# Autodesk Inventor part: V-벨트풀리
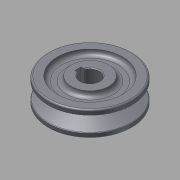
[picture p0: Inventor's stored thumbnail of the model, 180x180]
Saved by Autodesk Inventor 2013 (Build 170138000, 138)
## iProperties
Created: 2015-12
Part Number: V-벨트풀리
Material: 강철, 연강
Document SubType Name: Modeling
Designer: mdu
Density: 7.86 g/cm^3
Mass: 156.955 g
Surface Area: 99.5161 cm^2
Volume: 19.9688 cm^3
CustomPartVersion: 1
Author: mdu
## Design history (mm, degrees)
sketch "주 스케치"
  geometry: L1 (0, 16)-(27, 16); L2 (27, 16)-(27, 12.861); L3 (27, 12.861)-(16, 9.498); L4 (16, 9.498)-(16, 6.502); L5 (16, 6.502)-(27, 3.139); L6 (27, 3.139)-(27, 0); L7 (27, 0)-(0, 0); L8 (25, 12.25)-(25, 3.75); L9 (16, 8)-(25, 8); L10 (27, 12.861)-(27, 3.139); L11 (0, -3)-(0, 18) reference; L12 (0, 0)-(0, 16)
  constraints: 22 end point, 5 perpendicular, 2 collinear, 2 midpoint, 2 point on line, 1 parallel
  dimensions: "d0" = 8.5 distance of L8.start L8.end (= da_Bw); "d1" = 34 deg angle of L3 L5 (= da_Alfa); "d2" = 2 distance between parallel lines of L2 L8 (= da_c); "d6" = 16 distance between parallel lines of L7 L1 (computed from d5, da_ng, da_Sg); "d21" = 50 diameter of L8 L11 (= da_Dw); "d25" = 11 distance between parallel lines of L4 L10 (= da_Hd); "d27" = 8 distance between parallel lines of L7 L9 (= da_Se)
node "벨트 평면"
revolve "본체" stored, may be unused: angle "d7" = 90 deg
revolve "그루브" stored, may be unused: angle "d15" = 90 deg
feature "허브 키홈"
fillet "모깎기3" dims "d28" = 0.5, "d29" = 1, "d30" = 1
sketch "스케치2"
  geometry: C1 r 12 at (0, 0); C2 r 21 at (0, 0); 1 further point
  constraints: 2 centre point, 2 coincident
  dimensions: "d31" = 24 diameter of C1; "d32" = 42 diameter of C2
extrude "돌출1" cut sketch "스케치2" distance "d33" = 3; taper "d34" = 0 deg
fillet "모깎기4" dims "d35" = 3
node "작업 평면2"
chamfer "모따기1" distance "d36" = 0.5; stored, may be unused: second distance "d37" = 2, angle "d38" = 45 deg
body "Solid1"
pattern_linear "그루브 패턴" dims "d18" = 12 (= da_Sg)
mirror "대칭1"
other parameters: "d5" = 8 (= da_Se), "da_Bw" = 8.5 [user parameter; used in 1 equation term], "da_Alfa" = 34 deg [user parameter; used in 1 equation term], "da_c" = 2 [user parameter; used in 1 equation term], "da_Dw" = 50 [user parameter; used in 1 equation term], "da_Hd" = 11 [user parameter; used in 1 equation term], "da_Se" = 8 [user parameter; used in 2 equation terms], "da_Sg" = 12 [user parameter; used in 2 equation terms], "da_r1" = 0 [user parameter], "da_r2" = 0 [user parameter], "d24" = 0, "d26" = 0
